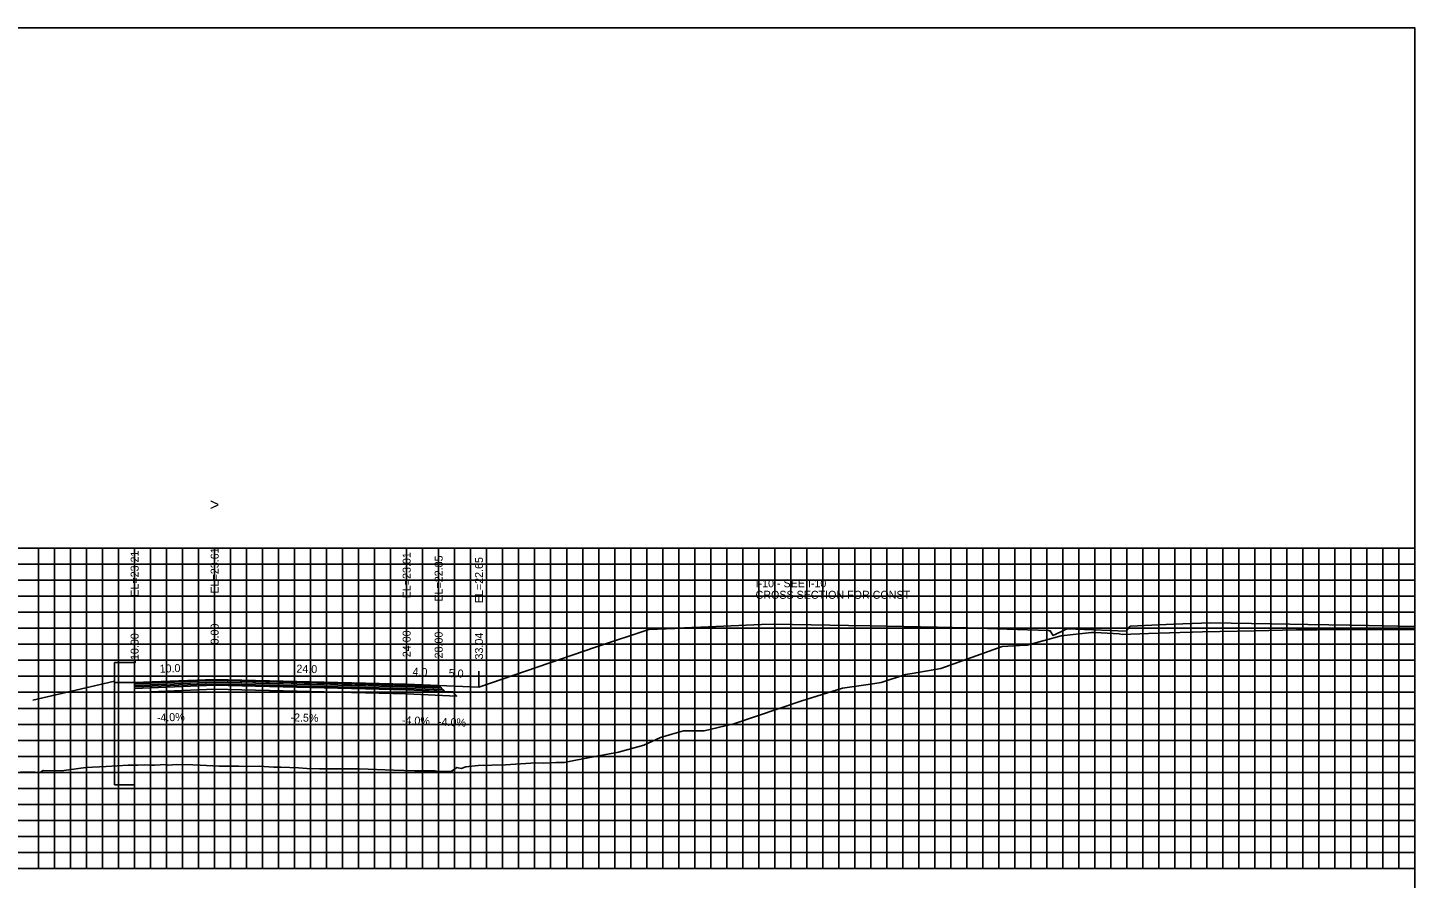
# Model space of a CAD drawing. Extents: x 1797518 to 1804843, y 248068 to 251132.
# Drawn here: x 1803287.6 to 1803461.1, y 250163.2 to 250269.4 of the extents above; entities that cross this region are included whole.
import ezdxf

# ---------------------------------------------------------------- set-up
doc = ezdxf.new("R2010")
doc.units = 0
for name, color, linetype in [('3', 7, 'Continuous'), ('4', 7, 'Continuous'), ('60', 7, 'Continuous'), ('BASE', 7, 'Continuous'), ('CL-CNST', 7, 'Continuous'), ('Level 62', 7, 'Continuous'), ('LOWER BINDER', 7, 'Continuous'), ('M-ROADS', 7, 'Continuous'), ('UPPER BINDER', 7, 'Continuous'), ('WEARING', 7, 'Continuous')]:
    doc.layers.add(name, color=color, linetype=linetype)

msp = doc.modelspace()

# ---------------------------------------------------------------- linework, layer by layer
for p, q in [((1803301, 250187.64), (1803301, 250189.64)), ((1803311, 250188.04), (1803311, 250190.04)), ((1803335, 250187.45), (1803335, 250189.45)), ((1803339, 250187.29), (1803339, 250189.29)), ((1803344.04, 250187.08), (1803344.04, 250189.08))]:
    msp.add_line(p, q)
msp.add_lwpolyline([(1803161, 250079.43), (1803461, 250079.43), (1803461, 250269.43), (1803161, 250269.43)], close=True)
at = {"layer": '3'}
msp.add_line((1803288.28, 250185.43), (1803298.5, 250187.82), dxfattribs=at)
at = {"layer": '60'}
for p, q in [((1803461, 250164.43), (1803461, 250204.43)), ((1803461.06, 250204.43), (1803461, 250204.43)), ((1803461.06, 250194.43), (1803461, 250194.43)), ((1803461.06, 250184.43), (1803461, 250184.43)), ((1803461.06, 250174.43), (1803461, 250174.43)), ((1803161, 250164.43), (1803461, 250164.43)), ((1803291, 250164.37), (1803291, 250164.43)), ((1803301, 250164.37), (1803301, 250164.43)), ((1803311, 250164.37), (1803311, 250164.43)), ((1803321, 250164.37), (1803321, 250164.43)), ((1803331, 250164.37), (1803331, 250164.43)), ((1803341, 250164.37), (1803341, 250164.43)), ((1803351, 250164.37), (1803351, 250164.43)), ((1803361, 250164.37), (1803361, 250164.43)), ((1803371, 250164.37), (1803371, 250164.43)), ((1803381, 250164.37), (1803381, 250164.43)), ((1803391, 250164.37), (1803391, 250164.43)), ((1803401, 250164.37), (1803401, 250164.43)), ((1803411, 250164.37), (1803411, 250164.43)), ((1803421, 250164.37), (1803421, 250164.43)), ((1803431, 250164.37), (1803431, 250164.43)), ((1803441, 250164.37), (1803441, 250164.43)), ((1803451, 250164.37), (1803451, 250164.43)), ((1803461, 250164.37), (1803461, 250164.43)), ((1803461.06, 250164.43), (1803461, 250164.43))]:
    msp.add_line(p, q, dxfattribs=at)
at = {"layer": 'BASE'}
msp.add_lwpolyline([(1803301, 250186.92), (1803311, 250187.32), (1803335, 250186.73), (1803339.75, 250186.54), (1803340.75, 250186.5), (1803341.27, 250185.97), (1803335, 250186.23), (1803311, 250186.82), (1803301, 250186.42)], close=True, dxfattribs=at)
at = {"layer": 'CL-CNST'}
for points in [[(1803344.04, 250187.08), (1803358.74, 250192.11), (1803365.26, 250194.28), (1803368.54, 250194.42), (1803368.8, 250194.44), (1803370.64, 250194.51), (1803370.82, 250194.52), (1803379.37, 250194.89), (1803380.91, 250194.95), (1803390.21, 250194.78), (1803393.02, 250194.73), (1803401.32, 250194.58), (1803405.14, 250194.5), (1803411.3, 250194.28), (1803415.23, 250194.14), (1803415.36, 250194.13), (1803415.45, 250194.13), (1803415.64, 250193.78), (1803415.78, 250193.53), (1803416.76, 250194), (1803417.5, 250194.36), (1803420.85, 250194.23), (1803424.91, 250194.08), (1803425.18, 250194.39), (1803425.45, 250194.7), (1803430.85, 250194.93), (1803435.53, 250195.13), (1803443.12, 250194.99), (1803447.62, 250194.91), (1803452.9, 250194.81), (1803455.23, 250194.76), (1803461, 250194.66)], [(1803301, 250187.64), (1803311, 250188.04), (1803335, 250187.45), (1803339, 250187.29), (1803344.04, 250187.08)]]:
    msp.add_lwpolyline(points, dxfattribs=at)
for points in [[(1803301, 250187.64), (1803298.5, 250187.64), (1803298.5, 250190.14), (1803301, 250190.14)], [(1803298.5, 250174.87), (1803301, 250174.87), (1803301, 250187.64), (1803298.5, 250187.64)]]:
    msp.add_lwpolyline(points, close=True, dxfattribs=at)
at = {"layer": 'Level 62'}
for p, q in [((1803161, 250204.43), (1803461, 250204.43)), ((1803289, 250164.43), (1803289, 250204.43)), ((1803291, 250164.43), (1803291, 250204.43)), ((1803293, 250164.43), (1803293, 250204.43)), ((1803295, 250164.43), (1803295, 250204.43)), ((1803297, 250164.43), (1803297, 250204.43)), ((1803299, 250164.43), (1803299, 250204.43)), ((1803301, 250164.43), (1803301, 250204.43)), ((1803303, 250164.43), (1803303, 250204.43)), ((1803305, 250164.43), (1803305, 250204.43)), ((1803307, 250164.43), (1803307, 250204.43)), ((1803309, 250164.43), (1803309, 250204.43)), ((1803311, 250164.43), (1803311, 250204.43)), ((1803313, 250164.43), (1803313, 250204.43)), ((1803315, 250164.43), (1803315, 250204.43)), ((1803317, 250164.43), (1803317, 250204.43)), ((1803319, 250164.43), (1803319, 250204.43)), ((1803321, 250164.43), (1803321, 250204.43)), ((1803323, 250164.43), (1803323, 250204.43)), ((1803325, 250164.43), (1803325, 250204.43)), ((1803327, 250164.43), (1803327, 250204.43)), ((1803329, 250164.43), (1803329, 250204.43)), ((1803331, 250164.43), (1803331, 250204.43)), ((1803333, 250164.43), (1803333, 250204.43)), ((1803335, 250164.43), (1803335, 250204.43)), ((1803337, 250164.43), (1803337, 250204.43)), ((1803339, 250164.43), (1803339, 250204.43)), ((1803341, 250164.43), (1803341, 250204.43)), ((1803343, 250164.43), (1803343, 250204.43)), ((1803345, 250164.43), (1803345, 250204.43)), ((1803347, 250164.43), (1803347, 250204.43)), ((1803349, 250164.43), (1803349, 250204.43)), ((1803351, 250164.43), (1803351, 250204.43)), ((1803353, 250164.43), (1803353, 250204.43)), ((1803355, 250164.43), (1803355, 250204.43)), ((1803357, 250164.43), (1803357, 250204.43)), ((1803359, 250164.43), (1803359, 250204.43)), ((1803361, 250164.43), (1803361, 250204.43)), ((1803363, 250164.43), (1803363, 250204.43)), ((1803365, 250164.43), (1803365, 250204.43)), ((1803367, 250164.43), (1803367, 250204.43)), ((1803369, 250164.43), (1803369, 250204.43)), ((1803371, 250164.43), (1803371, 250204.43)), ((1803373, 250164.43), (1803373, 250204.43)), ((1803375, 250164.43), (1803375, 250204.43)), ((1803377, 250164.43), (1803377, 250204.43)), ((1803379, 250164.43), (1803379, 250204.43)), ((1803381, 250164.43), (1803381, 250204.43)), ((1803383, 250164.43), (1803383, 250204.43)), ((1803385, 250164.43), (1803385, 250204.43)), ((1803387, 250164.43), (1803387, 250204.43)), ((1803389, 250164.43), (1803389, 250204.43)), ((1803391, 250164.43), (1803391, 250204.43)), ((1803393, 250164.43), (1803393, 250204.43)), ((1803395, 250164.43), (1803395, 250204.43)), ((1803397, 250164.43), (1803397, 250204.43)), ((1803399, 250164.43), (1803399, 250204.43)), ((1803401, 250164.43), (1803401, 250204.43)), ((1803403, 250164.43), (1803403, 250204.43)), ((1803405, 250164.43), (1803405, 250204.43)), ((1803407, 250164.43), (1803407, 250204.43)), ((1803409, 250164.43), (1803409, 250204.43)), ((1803411, 250164.43), (1803411, 250204.43)), ((1803413, 250164.43), (1803413, 250204.43)), ((1803415, 250164.43), (1803415, 250204.43)), ((1803417, 250164.43), (1803417, 250204.43)), ((1803419, 250164.43), (1803419, 250204.43)), ((1803421, 250164.43), (1803421, 250204.43)), ((1803423, 250164.43), (1803423, 250204.43)), ((1803425, 250164.43), (1803425, 250204.43)), ((1803427, 250164.43), (1803427, 250204.43)), ((1803429, 250164.43), (1803429, 250204.43)), ((1803431, 250164.43), (1803431, 250204.43)), ((1803433, 250164.43), (1803433, 250204.43)), ((1803435, 250164.43), (1803435, 250204.43)), ((1803437, 250164.43), (1803437, 250204.43)), ((1803439, 250164.43), (1803439, 250204.43)), ((1803441, 250164.43), (1803441, 250204.43)), ((1803443, 250164.43), (1803443, 250204.43)), ((1803445, 250164.43), (1803445, 250204.43)), ((1803447, 250164.43), (1803447, 250204.43)), ((1803449, 250164.43), (1803449, 250204.43)), ((1803451, 250164.43), (1803451, 250204.43)), ((1803453, 250164.43), (1803453, 250204.43)), ((1803455, 250164.43), (1803455, 250204.43)), ((1803457, 250164.43), (1803457, 250204.43)), ((1803459, 250164.43), (1803459, 250204.43)), ((1803461, 250164.43), (1803461, 250204.43)), ((1803161, 250202.43), (1803461, 250202.43)), ((1803161, 250200.43), (1803461, 250200.43)), ((1803161, 250198.43), (1803461, 250198.43)), ((1803161, 250196.43), (1803461, 250196.43)), ((1803161, 250194.43), (1803461, 250194.43)), ((1803161, 250192.43), (1803461, 250192.43)), ((1803161, 250190.43), (1803461, 250190.43)), ((1803161, 250188.43), (1803461, 250188.43)), ((1803161, 250186.43), (1803461, 250186.43)), ((1803161, 250184.43), (1803461, 250184.43)), ((1803161, 250182.43), (1803461, 250182.43)), ((1803161, 250180.43), (1803461, 250180.43)), ((1803161, 250178.43), (1803461, 250178.43)), ((1803161, 250176.43), (1803461, 250176.43)), ((1803161, 250174.43), (1803461, 250174.43)), ((1803161, 250172.43), (1803461, 250172.43)), ((1803161, 250170.43), (1803461, 250170.43)), ((1803161, 250168.43), (1803461, 250168.43)), ((1803161, 250166.43), (1803461, 250166.43)), ((1803161, 250164.43), (1803461, 250164.43))]:
    msp.add_line(p, q, dxfattribs=at)
at = {"layer": 'LOWER BINDER'}
for points in [[(1803311, 250187.7), (1803335, 250187.11), (1803339.36, 250186.93), (1803339.55, 250186.73), (1803335, 250186.92), (1803311, 250187.51), (1803301, 250187.11), (1803301, 250187.3)], [(1803311, 250187.51), (1803335, 250186.92), (1803339.55, 250186.73), (1803339.75, 250186.54), (1803335, 250186.73), (1803311, 250187.32), (1803301, 250186.92), (1803301, 250187.11)]]:
    msp.add_lwpolyline(points, close=True, dxfattribs=at)
at = {"layer": 'M-ROADS'}
msp.add_lwpolyline([(1803286.74, 250176.46), (1803288.53, 250176.46), (1803288.95, 250176.39), (1803289.24, 250176.46), (1803289.49, 250176.63), (1803289.51, 250176.66), (1803289.53, 250176.66), (1803289.6, 250176.66), (1803291.83, 250176.64), (1803292.76, 250176.76), (1803294.91, 250177.05), (1803297.44, 250177.16), (1803300.21, 250177.33), (1803301.41, 250177.33), (1803302.26, 250177.39), (1803302.85, 250177.34), (1803303.01, 250177.34), (1803303.09, 250177.33), (1803303.38, 250177.35), (1803303.5, 250177.34), (1803304.9, 250177.41), (1803305.2, 250177.33), (1803306.28, 250177.41), (1803308.29, 250177.39), (1803309.21, 250177.33), (1803311.55, 250177.19), (1803313.47, 250177.2), (1803314.03, 250177.19), (1803315.14, 250177.17), (1803316.55, 250177.19), (1803318.38, 250177.1), (1803319.28, 250177.07), (1803321.47, 250176.98), (1803322.52, 250176.93), (1803324.12, 250176.86), (1803325.63, 250176.87), (1803326.64, 250176.87), (1803327.3, 250176.86), (1803329.12, 250176.86), (1803333.4, 250176.72), (1803336.02, 250176.62), (1803337.14, 250176.62), (1803338.55, 250176.61), (1803338.73, 250176.59), (1803340.55, 250176.55), (1803341.29, 250177.04), (1803341.82, 250176.91), (1803342.39, 250177.11), (1803343.94, 250177.3), (1803347.37, 250177.38), (1803351.16, 250177.62), (1803352.14, 250177.59), (1803353.65, 250177.66), (1803354.18, 250177.66), (1803354.7, 250177.66), (1803356.15, 250177.94), (1803358.57, 250178.4), (1803361.46, 250178.96), (1803364.63, 250179.82), (1803366.71, 250180.8), (1803368.14, 250181.21), (1803369.62, 250181.63), (1803370.91, 250181.63), (1803372.19, 250181.63), (1803374.79, 250182.24), (1803375.91, 250182.5), (1803384.38, 250185.37), (1803389.49, 250186.96), (1803392.96, 250187.45), (1803394.32, 250187.64), (1803397.35, 250188.66), (1803398.19, 250188.8), (1803401.76, 250189.41), (1803409.43, 250192.16), (1803411.58, 250192.28), (1803412.56, 250192.33), (1803416.8, 250193.49), (1803420.61, 250193.9), (1803420.84, 250193.9), (1803421.07, 250193.9), (1803424.06, 250193.72), (1803424.42, 250193.67), (1803427.71, 250193.77), (1803432.98, 250193.93), (1803433.2, 250193.93), (1803433.23, 250193.93), (1803434.46, 250193.97), (1803441.01, 250194.11), (1803446.24, 250194.24), (1803448.79, 250194.25), (1803457.72, 250194.27), (1803458.26, 250194.27), (1803458.42, 250194.27), (1803461, 250194.24)], dxfattribs=at)
at = {"layer": 'UPPER BINDER'}
msp.add_lwpolyline([(1803339.36, 250186.93), (1803339.16, 250187.13), (1803335, 250187.3), (1803311, 250187.89), (1803301, 250187.49), (1803301, 250187.3), (1803311, 250187.7), (1803335, 250187.11)], close=True, dxfattribs=at)
at = {"layer": 'WEARING'}
msp.add_lwpolyline([(1803339.16, 250187.13), (1803339, 250187.29), (1803335, 250187.45), (1803311, 250188.04), (1803311, 250188.04), (1803301, 250187.64), (1803301, 250187.49), (1803311, 250187.89), (1803335, 250187.3)], close=True, dxfattribs=at)

# ---------------------------------------------------------------- texts
at = {"layer": '3'}
for s, p in [('EL=23.61', (1803311.5, 250198.77)), ('EL=23.21', (1803301.5, 250198.37)), ('EL=23.01', (1803335.5, 250198.17)), ('EL=22.85', (1803339.5, 250197.76)), ('EL=22.65', (1803344.54, 250197.56)), ('-10.00', (1803301.5, 250190.02)), ('0.00', (1803311.5, 250192.41)), ('24.00', (1803335.5, 250190.82)), ('28.00', (1803339.5, 250190.66)), ('33.04', (1803344.54, 250190.53))]:
    msp.add_text(s, height=1, rotation=90, dxfattribs=at).set_placement(p)
for s, p in [('CROSS SECTION FOR CONST ', (1803378.61, 250198.11)), ('I-10 - SEE I-10', (1803378.61, 250199.55))]:
    msp.add_text(s, height=1, dxfattribs=at).set_placement(p)
at = {"layer": '4'}
for s, rotation, p in [('10.0', 2.2906, (1803304.14, 250188.87)), ('24.0', 358.5689, (1803321.21, 250188.89)), ('4.0', 357.7094, (1803335.72, 250188.52)), ('5.0', 357.7094, (1803340.24, 250188.34)), ('-4.0%', 2.2906, (1803303.79, 250182.75)), ('-2.5%', 358.5689, (1803320.47, 250182.81)), ('-4.0%', 357.7094, (1803334.39, 250182.47)), ('-4.0%', 357.7094, (1803338.91, 250182.28))]:
    msp.add_text(s, height=1, rotation=rotation, dxfattribs=at).set_placement(p)
at = {"layer": '60'}
msp.add_text('>', height=1.5, dxfattribs=at).set_placement((1803310.39, 250209.15))

doc.saveas('drawing.dxf')
